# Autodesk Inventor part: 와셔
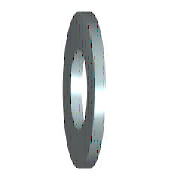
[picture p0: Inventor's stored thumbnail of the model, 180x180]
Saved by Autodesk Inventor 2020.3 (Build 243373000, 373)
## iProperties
IsCustomPart: 1
Created: 2012-02
Part Number: 와셔
Material: 강철, 연강
Description: 평면 와셔
Document SubType Name: Modeling
Standard: KS B 1326
Designer: mduedu
Standards Organization: KS
Language: ko-KR
Size Designation: 8x15.5
Categories: <MemberInstance><Categories><Category DisplayName="조임쇠" InternalName="e4da775c-781d-43d5-af7c-5136215cf5a6" Mnemonic="FSTN"><Category DisplayName="와셔" InternalN
Density: 1 g/cm^3
Appearance: 주황색
Author: mduedu
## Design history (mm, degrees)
sketch "스케치"
  geometry: C1 r 7.75 at (0, 0); C2 r 4.2 at (0, 0); 1 further point
  constraints: 2 centre point, 2 coincident
  dimensions: "d0" = 8.4 diameter of C2 (= SD1); "d1" = 15.5 diameter of C1 (= SD2)
extrude "본체" new body sketch "스케치" distance "d2" = 1.6 (= SD); taper "d3" = 0 deg
workaxis "Work Axis1"
workplane "Work Plane1"
body "Solid1"
other parameters: "SD1" = 8.4 [user parameter; used in 1 equation term], "SD2" = 15.5 [user parameter; used in 1 equation term], "SD" = 1.6 [user parameter; used in 1 equation term], "d4" = 0, "d5" = 0, "d6" = 0, "d7" = 0, "NND" = 8 [user parameter]
